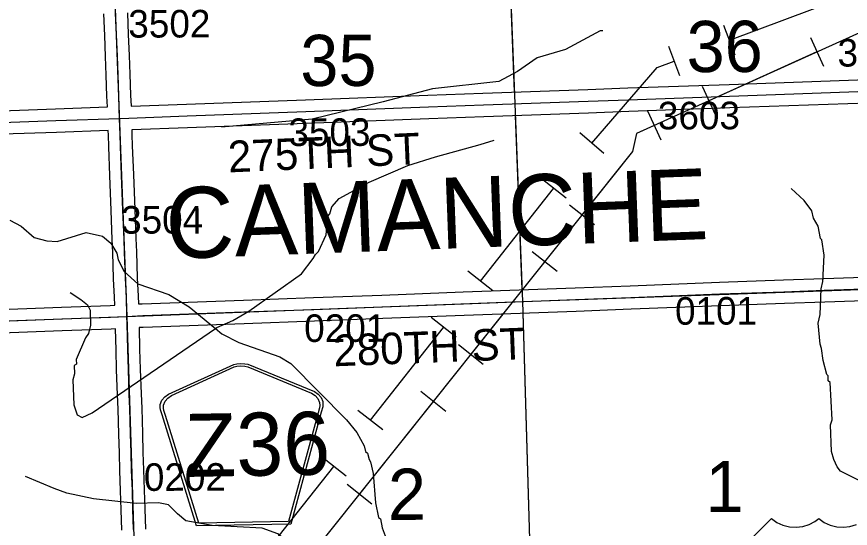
# Model space of a CAD drawing. Extents: x 128.7 to 185.5, y -21.4 to 12.6.
# Drawn here: x 162.114 to 164.229, y -13.284 to -11.985 of the extents above; entities that cross this region are included whole.
import ezdxf

# ---------------------------------------------------------------- set-up
doc = ezdxf.new("R2010")
doc.units = 0
for name, color, linetype in [('tdCoHydroRiver', 7, 'Continuous'), ('tdCoPipe', 7, 'Continuous'), ('tdCoPipe1', 7, 'Continuous'), ('tdCoPipe2', 7, 'Continuous'), ('tdCoSecRdNmbr', 7, 'Continuous'), ('tdCoSecRdTxt', 7, 'Continuous'), ('tdCoSecRteBand', 7, 'Continuous'), ('tdCoSecRteCL', 7, 'Continuous'), ('tdCoSectLine', 7, 'Continuous'), ('tdCoSectLinePart', 7, 'Continuous'), ('tdCoSectNmbr', 7, 'Continuous'), ('tdCoShieldCoRteHrd', 7, 'Continuous'), ('tdCoShieldUsRte', 7, 'Continuous'), ('tdCoSurfAsphalt', 7, 'Continuous'), ('tdCoSurfGravel', 7, 'Continuous'), ('tdCoTwpBndryShd', 7, 'Continuous'), ('tdCoTwpNameTxt', 7, 'Continuous')]:
    doc.layers.add(name, color=color, linetype=linetype)

msp = doc.modelspace()

# ---------------------------------------------------------------- linework, layer by layer
at = {"layer": 'tdCoHydroRiver'}
for points in [[(163.6006, -12.0207), (163.5943, -12.0209), (163.5059, -12.0682), (163.4341, -12.0896), (163.3848, -12.1244), (163.3367, -12.1498), (163.1685, -12.1682), (163.0433, -12.2009), (162.8633, -12.245), (162.6336, -12.2656)], [(162.2492, -12.685), (162.2767, -12.7029), (162.293, -12.7165), (162.2998, -12.7304), (162.3012, -12.7683), (162.2957, -12.789), (162.2882, -12.8003), (162.265, -12.8549), (162.2655, -12.8675), (162.2593, -12.8709), (162.2601, -12.8913), (162.2559, -12.9073), (162.2583, -12.9703), (162.2671, -12.9953), (162.28, -13.0027), (162.3048, -12.9907), (162.618, -12.7764), (162.6219, -12.7737), (162.6623, -12.7564), (162.7025, -12.7328), (162.8362, -12.6378), (162.8664, -12.5988), (162.8723, -12.5891), (162.8799, -12.5809), (162.8989, -12.5392), (162.9034, -12.4916), (162.9079, -12.4851), (162.9136, -12.4676), (162.9318, -12.4462), (163.0079, -12.405), (163.1062, -12.3629), (163.1767, -12.3409), (163.2896, -12.3092), (163.3256, -12.2982)], [(164.2649, -13.1692), (164.2038, -13.1384), (164.1955, -13.1276), (164.1869, -13.109), (164.1814, -13.0887), (164.1788, -13.0209), (164.1831, -13.0081), (164.178, -12.9136), (164.1731, -12.909), (164.1726, -12.8964), (164.1694, -12.8934), (164.1601, -12.8574), (164.1558, -12.8276), (164.1523, -12.8167), (164.1471, -12.7632), (164.1526, -12.7409), (164.1549, -12.6761), (164.1589, -12.657), (164.1628, -12.5905), (164.1566, -12.5513), (164.1533, -12.5483), (164.1474, -12.5169), (164.1356, -12.4969), (164.1317, -12.478), (164.1118, -12.452), (164.0791, -12.4216)], [(162.0963, -12.502), (162.1252, -12.5167), (162.1579, -12.5454), (162.1898, -12.5537), (162.2167, -12.5559), (162.29, -12.5326), (162.3314, -12.5421), (162.3526, -12.5603), (162.3677, -12.585), (162.3715, -12.6022), (162.3868, -12.6316), (162.4212, -12.6635), (162.4995, -12.6905), (162.5512, -12.7218), (162.618, -12.7764), (162.6343, -12.7897), (162.6777, -12.8118), (162.7817, -12.8489), (162.8091, -12.8653), (162.9502, -13.0084), (162.9767, -13.0405), (162.9953, -13.0746), (162.999, -13.0886), (163.0039, -13.0932), (163.0077, -13.1088), (163.0111, -13.115), (163.0185, -13.1447), (163.0244, -13.2187), (163.0321, -13.2563), (163.037, -13.2593), (163.041, -13.2828), (163.0515, -13.3093)], [(163.1527, -13.3576), (163.0975, -13.3596), (163.0221, -13.3672), (162.929, -13.3707), (162.8783, -13.3647), (162.8415, -13.3518), (162.7763, -13.2974), (162.7363, -13.2831), (162.6098, -13.2768), (162.5431, -13.2651), (162.5219, -13.247), (162.4989, -13.2241), (162.4735, -13.2188), (162.4167, -13.2209), (162.3089, -13.2091), (162.2405, -13.1943), (162.2085, -13.1829), (162.1363, -13.1524)]]:
    msp.add_lwpolyline(points, dxfattribs=at)
at = {"layer": 'tdCoPipe'}
msp.add_lwpolyline([(164.5574, -11.8875), (163.6862, -12.2814), (163.6759, -12.3273), (162.8211, -13.4003), (161.9826, -14.6801), (161.6282, -15.7116)], dxfattribs=at)
at = {"layer": 'tdCoPipe1'}
for p, q in [((164.1277, -12.0376), (164.1609, -12.1109)), ((163.8533, -12.1616), (163.8865, -12.2351)), ((163.7147, -12.2243), (163.7478, -12.2976)), ((163.5168, -12.4623), (163.5799, -12.5125)), ((163.4221, -12.5813), (163.485, -12.6314)), ((163.2344, -12.8168), (163.2975, -12.8671)), ((163.1396, -12.9358), (163.2026, -12.986)), ((162.9519, -13.1714), (163.015, -13.2216))]:
    msp.add_line(p, q, dxfattribs=at)
for points in [[(164.1443, -12.0743), (163.8699, -12.1984)], [(163.7313, -12.261), (163.6862, -12.2814), (163.6759, -12.3273), (163.5484, -12.4874)], [(163.4536, -12.6064), (163.2659, -12.8419)], [(163.1711, -12.9609), (162.9835, -13.1965)]]:
    msp.add_lwpolyline(points, dxfattribs=at)
at = {"layer": 'tdCoPipe2'}
for p, q in [((163.9367, -12.0825), (163.9084, -12.0074)), ((163.7964, -12.1354), (163.7681, -12.0604)), ((163.6035, -12.3325), (163.5428, -12.2802)), ((163.5077, -12.4456), (163.4448, -12.3959)), ((163.3216, -12.681), (163.2587, -12.6313)), ((163.2286, -12.7986), (163.1657, -12.7489)), ((163.0425, -13.034), (162.9796, -12.9843)), ((162.9495, -13.1516), (162.8866, -13.1019))]:
    msp.add_line(p, q, dxfattribs=at)
for points in [[(163.9226, -12.0449), (164.2032, -11.9391)], [(163.5731, -12.3063), (163.7387, -12.1143), (163.7822, -12.0979)], [(163.2902, -12.6561), (163.4762, -12.4208)], [(163.0111, -13.0091), (163.1971, -12.7738)], [(162.732, -13.3621), (162.918, -13.1268)]]:
    msp.add_lwpolyline(points, dxfattribs=at)
at = {"layer": 'tdCoSecRteBand'}
for points in [[(162.0752, -12.2237), (162.2123, -12.2187), (162.2123, -12.2187), (162.2123, -12.2187), (162.3438, -12.2142), (162.3428, -12.187), (162.3428, -12.187), (162.3428, -12.1869), (162.3409, -12.1334), (162.3393, -12.0862), (162.337, -12.0328), (162.337, -12.0328), (162.337, -12.0328), (162.3347, -11.9776)], [(162.3947, -11.9752), (162.3969, -12.0303), (162.3992, -12.0838), (162.3992, -12.0839), (162.3992, -12.084), (162.4009, -12.1313), (162.4009, -12.1313), (162.4009, -12.1313), (162.4027, -12.1847), (162.4038, -12.2121), (162.5449, -12.2069), (162.5449, -12.2069), (162.5449, -12.2069), (162.8463, -12.1961), (163.1572, -12.1842), (163.1572, -12.1842), (163.1572, -12.1842), (163.2968, -12.179), (163.2968, -12.179), (163.2969, -12.179), (163.5627, -12.1697), (163.6645, -12.166), (163.6645, -12.166), (163.6645, -12.166), (163.9213, -12.1568), (164.2707, -12.1443)], [(164.2727, -12.2042), (163.9234, -12.2168), (163.9234, -12.2168), (163.9234, -12.2168), (163.6667, -12.2259), (163.5648, -12.2296), (163.5648, -12.2296), (163.5648, -12.2296), (163.299, -12.239), (163.1595, -12.2442), (162.8485, -12.256), (162.8485, -12.256), (162.8484, -12.256), (162.5471, -12.2669), (162.4059, -12.2721), (162.4059, -12.2721), (162.4058, -12.2721), (162.4062, -12.2842), (162.4062, -12.2843), (162.4062, -12.2844), (162.4071, -12.3129), (162.4099, -12.3859), (162.4099, -12.3859), (162.41, -12.3859), (162.4133, -12.4747), (162.4161, -12.5483), (162.4161, -12.5483), (162.4161, -12.5483), (162.4174, -12.5816), (162.4174, -12.5816), (162.4174, -12.5817), (162.4197, -12.6478), (162.4219, -12.6942), (162.4219, -12.6946), (162.4219, -12.6949), (162.4225, -12.7143), (162.4319, -12.7138), (162.4322, -12.7138), (162.4324, -12.7138), (162.6891, -12.7046), (162.8669, -12.698), (162.8669, -12.698), (162.8669, -12.698), (163.0405, -12.6916), (163.2466, -12.6837), (163.2467, -12.6837), (163.2467, -12.6837), (163.5307, -12.6733), (163.6705, -12.6679), (163.8971, -12.659), (163.8972, -12.659), (163.8972, -12.659), (164.0595, -12.6531), (164.0595, -12.6531), (164.0595, -12.6531), (164.1618, -12.6494), (164.1619, -12.6494), (164.1619, -12.6494), (164.3373, -12.6435)], [(162.0277, -12.7298), (162.2272, -12.7222), (162.2272, -12.7222), (162.2273, -12.7222), (162.3508, -12.718), (162.3625, -12.7174), (162.362, -12.6968), (162.3597, -12.6505), (162.3597, -12.6503), (162.3597, -12.65), (162.3574, -12.5838), (162.3562, -12.5506), (162.3533, -12.4771), (162.3533, -12.477), (162.3533, -12.477), (162.35, -12.3882), (162.3471, -12.3151), (162.3471, -12.315), (162.3471, -12.3148), (162.3463, -12.2862), (162.3459, -12.2742), (162.2144, -12.2787), (162.0773, -12.2836)], [(164.3391, -12.7035), (164.164, -12.7094), (164.0617, -12.7131), (163.8995, -12.719), (163.6729, -12.7279), (163.6729, -12.7279), (163.6729, -12.7279), (163.533, -12.7333), (163.533, -12.7333), (163.533, -12.7333), (163.2489, -12.7436), (163.0428, -12.7515), (163.0427, -12.7515), (163.0427, -12.7515), (162.8691, -12.7579), (162.6913, -12.7646), (162.6913, -12.7646), (162.6913, -12.7646), (162.4348, -12.7737), (162.4248, -12.7742), (162.4241, -12.7743), (162.4257, -12.8289), (162.4271, -12.8795), (162.4292, -12.9426), (162.4308, -12.9786), (162.4308, -12.9788), (162.4308, -12.9791), (162.4327, -13.0433), (162.4341, -13.0914), (162.4341, -13.0915), (162.4341, -13.0915), (162.4354, -13.135), (162.4372, -13.1865), (162.4372, -13.1866), (162.4372, -13.1867), (162.4387, -13.2346), (162.4403, -13.2862)], [(162.3804, -13.2881), (162.3787, -13.2365), (162.3787, -13.2364), (162.3787, -13.2364), (162.3773, -13.1886), (162.3754, -13.137), (162.3754, -13.1369), (162.3754, -13.1368), (162.3742, -13.0932), (162.3727, -13.0451), (162.3727, -13.0451), (162.3727, -13.0451), (162.3709, -12.9811), (162.3692, -12.9452), (162.3692, -12.945), (162.3692, -12.9448), (162.3671, -12.8814), (162.3671, -12.8813), (162.3671, -12.8812), (162.3657, -12.8306), (162.3642, -12.7774), (162.3536, -12.7779), (162.3534, -12.7779), (162.3531, -12.7779), (162.2294, -12.7821), (162.0299, -12.7898)]]:
    msp.add_lwpolyline(points, dxfattribs=at)
at = {"layer": 'tdCoSecRteCL'}
for points in [[(162.3748, -12.2431), (162.374, -12.2179), (162.3727, -12.1859), (162.3709, -12.1323), (162.3692, -12.085), (162.367, -12.0315), (162.3647, -11.9764), (162.3626, -11.9183), (162.3599, -11.8495), (162.3581, -11.7991), (162.3558, -11.7411)], [(162.3748, -12.2431), (162.3985, -12.2423), (162.546, -12.2369), (162.8474, -12.226), (163.1583, -12.2142), (163.2979, -12.209), (163.5638, -12.1997), (163.6656, -12.196), (163.9223, -12.1868), (164.2718, -12.1743), (164.2863, -12.1739)], [(160.3685, -12.3149), (160.3946, -12.3136), (160.5342, -12.3084), (160.7167, -12.3015), (160.9201, -12.2944), (161.0841, -12.2887), (161.3216, -12.2793), (161.3727, -12.2775), (161.4659, -12.2741), (161.6479, -12.2682), (161.8294, -12.262), (162.0762, -12.2537), (162.2133, -12.2487), (162.3748, -12.2431)], [(162.3933, -12.7458), (162.392, -12.6957), (162.3897, -12.649), (162.3874, -12.5827), (162.3862, -12.5494), (162.3833, -12.4759), (162.38, -12.3871), (162.3771, -12.3139), (162.3763, -12.2852), (162.3748, -12.2431)], [(162.3933, -12.7458), (162.4335, -12.7438), (162.6902, -12.7346), (162.868, -12.728), (163.0416, -12.7216), (163.2478, -12.7137), (163.5319, -12.7033), (163.6717, -12.6979), (163.8983, -12.689), (164.0606, -12.6831), (164.1629, -12.6794), (164.3383, -12.6735), (164.3886, -12.6722), (164.3966, -12.6721)], [(160.8912, -12.802), (160.9186, -12.801), (161.0515, -12.796), (161.1898, -12.7909), (161.3062, -12.7862), (161.392, -12.7829), (161.5413, -12.7773), (161.6535, -12.7731), (161.8581, -12.7655), (162.0288, -12.7598), (162.2283, -12.7521), (162.3521, -12.7479), (162.3933, -12.7458)], [(162.4103, -13.2872), (162.4087, -13.2355), (162.4072, -13.1876), (162.4054, -13.1359), (162.4041, -13.0923), (162.4027, -13.0442), (162.4008, -12.98), (162.3992, -12.9438), (162.3971, -12.8804), (162.3957, -12.8298), (162.3938, -12.7647), (162.3933, -12.7458)]]:
    msp.add_lwpolyline(points, dxfattribs=at)
at = {"layer": 'tdCoSectLine'}
for points in [[(163.358, -11.7031), (163.3969, -12.7082)], [(162.3554, -11.7411), (162.3929, -12.7458)], [(163.3969, -12.7082), (164.3962, -12.6721)], [(162.3929, -12.7458), (163.3969, -12.7082)], [(163.3969, -12.7082), (163.427, -13.7141)], [(161.3916, -12.7829), (162.3929, -12.7458)], [(162.3929, -12.7458), (162.4252, -13.7587)]]:
    msp.add_lwpolyline(points, dxfattribs=at)
at = {"layer": 'tdCoSectLinePart'}
for points in [[(163.3592, -11.7331), (163.3763, -12.1762)], [(163.3787, -12.2362), (163.3957, -12.6778)], [(163.3978, -12.7378), (163.427, -13.7141)]]:
    msp.add_lwpolyline(points, dxfattribs=at)
at = {"layer": 'tdCoShieldCoRteHrd'}
for points in [[(162.5699, -13.2773), (162.4831, -12.9959), (162.479, -12.9828), (162.4781, -12.9769), (162.478, -12.9691), (162.482, -12.9587), (162.4892, -12.9501), (162.4986, -12.9433), (162.6646, -12.868), (162.6721, -12.8662), (162.6825, -12.8651), (162.693, -12.8659), (162.7005, -12.8674), (162.869, -12.9368), (162.8787, -12.9433), (162.8861, -12.9517), (162.8905, -12.9619), (162.8907, -12.9697), (162.8901, -12.9756), (162.8864, -12.9888), (162.8094, -13.2731)], [(162.5757, -13.2709), (162.4912, -12.997), (162.4872, -12.9845), (162.4864, -12.9788), (162.4863, -12.9713), (162.4902, -12.9613), (162.497, -12.9531), (162.5061, -12.9465), (162.6654, -12.8743), (162.6726, -12.8726), (162.6826, -12.8715), (162.6926, -12.8722), (162.6999, -12.8737), (162.8617, -12.9403), (162.871, -12.9465), (162.8781, -12.9546), (162.8823, -12.9644), (162.8825, -12.9719), (162.8819, -12.9776), (162.8784, -12.9903), (162.8034, -13.2669)]]:
    msp.add_lwpolyline(points, close=True, dxfattribs=at)
at = {"layer": 'tdCoShieldUsRte'}
msp.add_lwpolyline([(163.9501, -13.3377), (164.0289, -13.2588), (164.0428, -13.2686), (164.0581, -13.2756), (164.0745, -13.2798), (164.0913, -13.2809), (164.1081, -13.2789), (164.1243, -13.2739), (164.1392, -13.2661), (164.149, -13.2588), (164.1628, -13.2686), (164.1781, -13.2756), (164.1945, -13.2798), (164.2114, -13.2809), (164.2281, -13.2789), (164.2443, -13.2739)], dxfattribs=at)
at = {"layer": 'tdCoSurfAsphalt'}
msp.add_lwpolyline([(162.4103, -13.2872), (162.4087, -13.2355), (162.4072, -13.1876), (162.4054, -13.1359), (162.4041, -13.0923), (162.4027, -13.0442), (162.4008, -12.98), (162.3992, -12.9438), (162.3971, -12.8804), (162.3957, -12.8298), (162.3938, -12.7647), (162.3933, -12.7458), (162.392, -12.6957), (162.3897, -12.649), (162.3874, -12.5827), (162.3862, -12.5494), (162.3833, -12.4759), (162.38, -12.3871), (162.3771, -12.3139), (162.3763, -12.2852), (162.3748, -12.2431), (162.374, -12.2179), (162.3727, -12.1859), (162.3709, -12.1323), (162.3692, -12.085), (162.367, -12.0315), (162.3647, -11.9764)], dxfattribs=at)
at = {"layer": 'tdCoSurfGravel'}
for points in [[(160.3685, -12.3149), (160.3946, -12.3136), (160.5342, -12.3084), (160.7167, -12.3015), (160.9201, -12.2944), (161.0841, -12.2887), (161.3216, -12.2793), (161.3727, -12.2775), (161.4659, -12.2741), (161.6479, -12.2682), (161.8294, -12.262), (162.0762, -12.2537), (162.2133, -12.2487), (162.3748, -12.2431), (162.3985, -12.2423), (162.546, -12.2369), (162.8474, -12.226), (163.1583, -12.2142), (163.2979, -12.209), (163.5638, -12.1997), (163.6656, -12.196), (163.9223, -12.1868), (164.2718, -12.1743), (164.2863, -12.1739)], [(162.3933, -12.7458), (162.4335, -12.7438), (162.6902, -12.7346), (162.868, -12.728), (163.0416, -12.7216), (163.2478, -12.7137), (163.5319, -12.7033), (163.6717, -12.6979), (163.8983, -12.689), (164.0606, -12.6831), (164.1629, -12.6794), (164.3383, -12.6735), (164.3886, -12.6722), (164.3966, -12.6721)], [(160.4744, -12.8175), (160.6697, -12.8103), (160.7425, -12.8079), (160.8912, -12.802), (160.9186, -12.801), (161.0515, -12.796), (161.1898, -12.7909), (161.3062, -12.7862), (161.392, -12.7829), (161.5413, -12.7773), (161.6535, -12.7731), (161.8581, -12.7655), (162.0288, -12.7598), (162.2283, -12.7521), (162.3521, -12.7479), (162.3933, -12.7458)]]:
    msp.add_lwpolyline(points, dxfattribs=at)
at = {"layer": 'tdCoTwpBndryShd'}
msp.add_lwpolyline([(158.2224, -7.8865), (159.2119, -7.8386), (160.2098, -7.7958), (161.2099, -7.7602), (162.2124, -7.7219), (162.2462, -8.7266), (162.2811, -9.726), (162.3153, -10.7365), (162.3554, -11.7411), (162.3929, -12.7458), (162.4252, -13.7587), (162.4594, -14.7462), (162.4837, -15.492)], dxfattribs=at)

# ---------------------------------------------------------------- texts
at = {"layer": 'tdCoSecRdNmbr'}
for s, rotation, p in [('3502', 0.122, (162.397, -12.0382)), ('3104', 0.1235, (164.1966, -12.1117)), ('3603', 0.123, (163.7408, -12.2712)), ('3503', 0.1223, (162.8032, -12.3134)), ('3504', 0.122, (162.3787, -12.5359)), ('0101', 0.1231, (163.7843, -12.767)), ('0201', 0.1224, (162.8433, -12.8108)), ('0202', 0.122, (162.4364, -13.1888))]:
    msp.add_text(s, height=0.07, rotation=rotation, dxfattribs=at).set_placement(p)
at = {"layer": 'tdCoSecRdTxt'}
for s, rotation, p in [('275TH ST', 2.4927, (162.6515, -12.3805)), ('280TH ST', 2.1831, (162.9187, -12.8727))]:
    msp.add_text(s, height=0.08, rotation=rotation, dxfattribs=at).set_placement(p)
at = {"layer": 'tdCoSectNmbr'}
for s, rotation, p in [('36', 0.1231, (163.8136, -12.1258)), ('35', 0.1223, (162.8334, -12.1612)), ('1', 0.123, (163.8615, -13.2428)), ('2', 0.1223, (163.0557, -13.2624))]:
    msp.add_text(s, height=0.13, rotation=rotation, dxfattribs=at).set_placement(p)
at = {"layer": 'tdCoShieldCoRteHrd'}
msp.add_text('Z36', height=0.16, rotation=1, dxfattribs=at).set_placement((162.5415, -13.1535))
at = {"layer": 'tdCoTwpNameTxt'}
msp.add_text('CAMANCHE', height=0.18, rotation=2.1228, dxfattribs=at).set_placement((162.4947, -12.6003))

doc.saveas('drawing.dxf')
